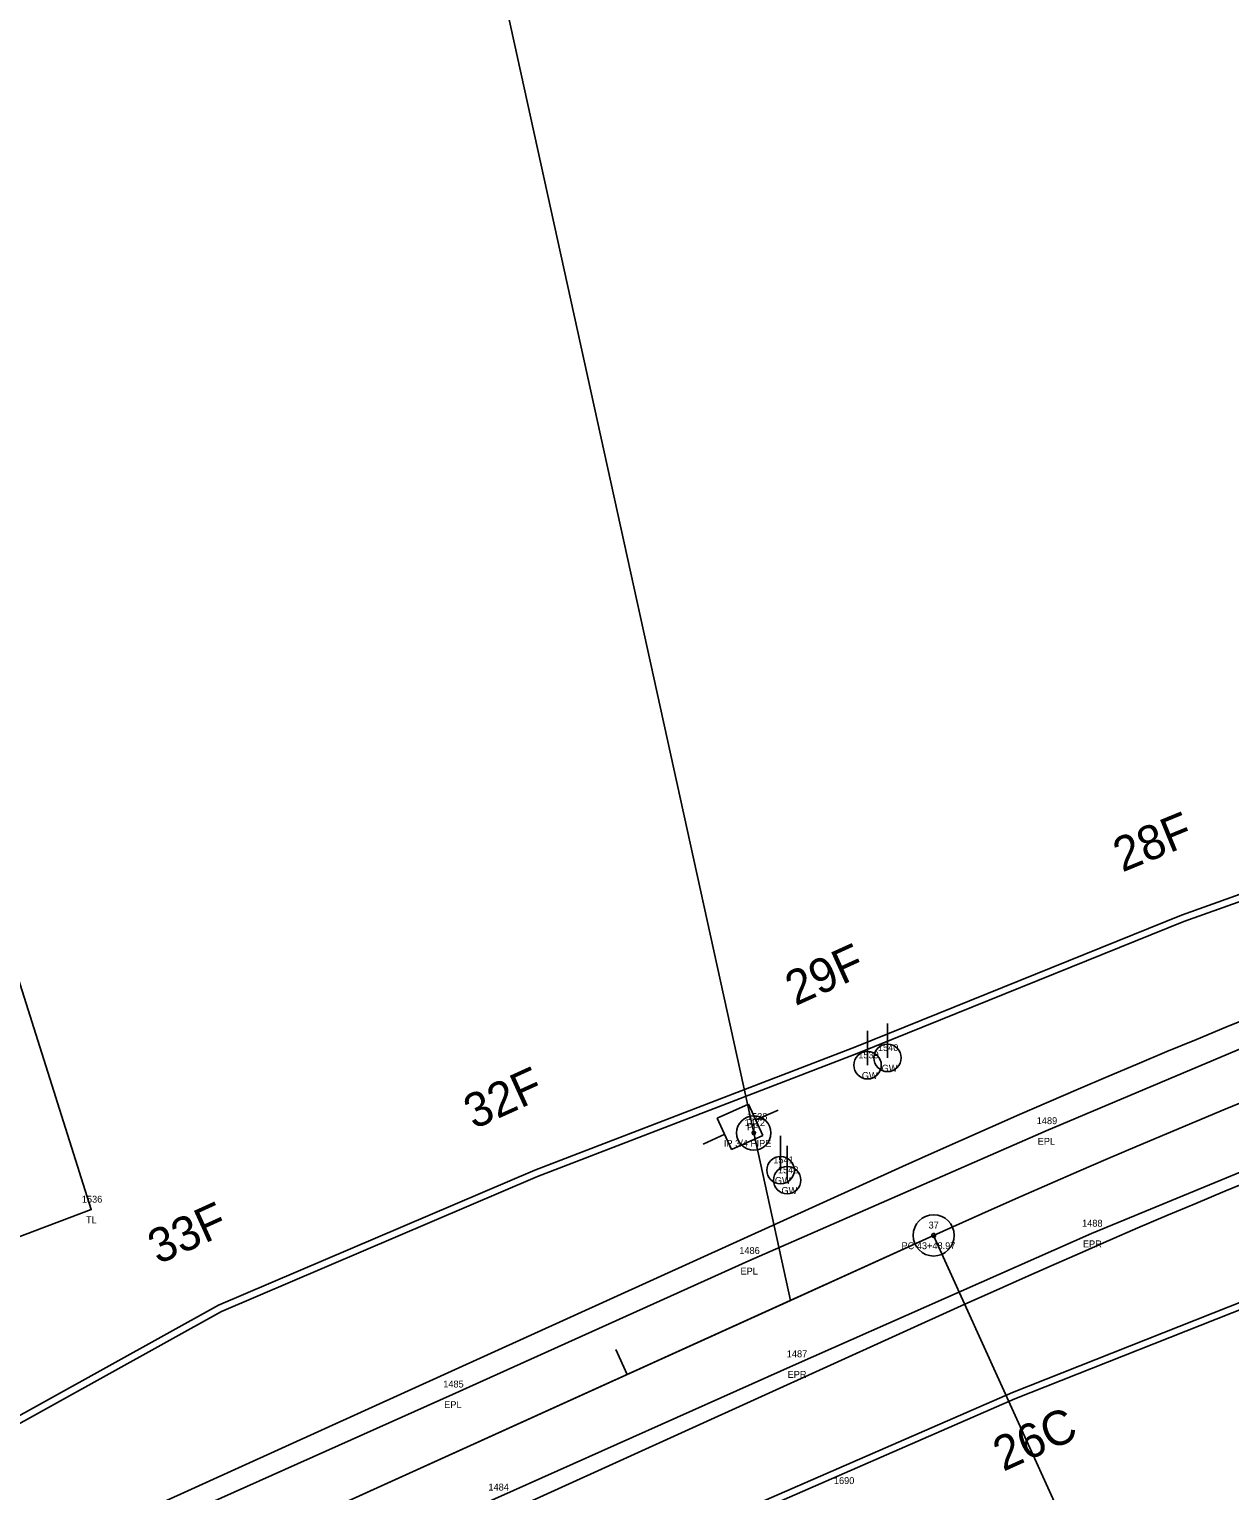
# Model space of a CAD drawing. Extents: x 1964982 to 1970452, y 1116335 to 1119906.
# Drawn here: x 1966013 to 1966187.8, y 1117238.1 to 1117450.8 of the extents above; entities that cross this region are included whole.
import ezdxf

# ---------------------------------------------------------------- set-up
doc = ezdxf.new("R2010")
doc.units = 0
for name, color, linetype in [('RD_EX_DV_Prop', 7, 'Continuous'), ('RD_EX_DV_Prop_txCode', 7, 'Continuous'), ('RD_EX_DV_PropPin', 7, 'Continuous'), ('RD_EX_Road', 7, 'Continuous'), ('RD_EX_Road_txCode', 7, 'Continuous'), ('RD_EX_RW', 7, 'Continuous'), ('RD_EX_UT', 7, 'Continuous'), ('RD_EX_UT_txCode', 7, 'Continuous'), ('RD_EX_VEG', 7, 'Continuous'), ('RD_EX_VEG_txCode', 7, 'Continuous'), ('RD_HC_CL', 7, 'Continuous'), ('RD_HC_Data', 7, 'Continuous'), ('RD_HC_Data_Tic', 7, 'Continuous'), ('RD_HC_txCode', 7, 'Continuous'), ('RD_PD_CstnLmt', 7, 'Continuous'), ('RD_PD_Final_TrvlWay', 7, 'Continuous'), ('RD_PD_RW', 7, 'Continuous'), ('RD_PD_TX_CstnLmt', 7, 'Continuous'), ('RD_SMD_Locator', 7, 'Continuous')]:
    doc.layers.add(name, color=color, linetype=linetype)

msp = doc.modelspace()

# ---------------------------------------------------------------- linework, layer by layer
at = {"layer": 'RD_EX_DV_Prop'}
for p, q in [((1965856.7, 1118481.39), (1966118.52, 1117290.19)), ((1966123.86, 1117265.83), (1966118.52, 1117290.19)), ((1966123.86, 1117265.83), (1966144.7, 1117275.28)), ((1966123.86, 1117265.83), (1965826.85, 1117131.21))]:
    msp.add_line(p, q, dxfattribs=at)
msp.add_arc((1966705.48, 1116038.04), 1358.39, 101.90473, 114.38256, dxfattribs=at)
at = {"layer": 'RD_EX_DV_PropPin'}
for radius in [2.5, 2.5, 0.25, 0.25]:
    msp.add_circle((1966118.52, 1117290.19), radius, dxfattribs=at)
at = {"layer": 'RD_EX_Road'}
for points in [[(1965729.99, 1117080.3), (1965819.77, 1117119.13), (1965907.74, 1117159.31), (1965995.36, 1117199.04), (1966039.27, 1117218.5), (1966081.24, 1117237.15), (1966124.67, 1117256.55), (1966167.66, 1117275.55), (1966211.47, 1117293.63), (1966257.79, 1117311.58), (1966302.7, 1117327.21), (1966347.9, 1117339.98), (1966394.81, 1117351.64), (1966441.56, 1117361.87), (1966488.62, 1117372.06), (1966534.91, 1117381.34), (1966581.23, 1117390.95), (1966629.53, 1117400.95), (1966675.63, 1117411.11), (1966721.68, 1117422.85), (1966766.8, 1117438.97), (1966775.75, 1117440.57)], [(1965723.84, 1117094.48), (1965813.3, 1117133.71), (1965900.46, 1117173.51), (1965988.47, 1117213.41), (1966031.82, 1117232.96), (1966074.66, 1117252.15), (1966117.78, 1117271.58), (1966161.06, 1117290.48), (1966205.41, 1117309.23), (1966251.25, 1117327.39), (1966297.25, 1117343.1), (1966344.08, 1117357.04)]]:
    msp.add_lwpolyline(points, dxfattribs=at)
at = {"layer": 'RD_EX_RW'}
for points in [[(1965729.99, 1117080.3), (1965819.77, 1117119.13), (1965907.74, 1117159.31), (1965995.36, 1117199.04), (1966039.27, 1117218.5), (1966081.24, 1117237.15), (1966124.67, 1117256.55), (1966167.66, 1117275.55), (1966211.47, 1117293.63), (1966257.79, 1117311.58), (1966302.7, 1117327.21), (1966347.9, 1117339.98), (1966394.81, 1117351.64), (1966441.56, 1117361.87), (1966488.62, 1117372.06), (1966534.91, 1117381.34), (1966581.23, 1117390.95), (1966629.53, 1117400.95), (1966675.63, 1117411.11), (1966721.68, 1117422.85), (1966766.8, 1117438.97), (1966775.75, 1117440.57)], [(1965723.84, 1117094.48), (1965813.3, 1117133.71), (1965900.46, 1117173.51), (1965988.47, 1117213.41), (1966031.82, 1117232.96), (1966074.66, 1117252.15), (1966117.78, 1117271.58), (1966161.06, 1117290.48), (1966205.41, 1117309.23), (1966251.25, 1117327.39), (1966297.25, 1117343.1), (1966344.08, 1117357.04)]]:
    msp.add_lwpolyline(points, dxfattribs=at)
at = {"layer": 'RD_EX_UT'}
for p, q in [((1966137.98, 1117301.12), (1966137.98, 1117306.12)), ((1966137.98, 1117301.12), (1966137.98, 1117306.12)), ((1966135.08, 1117300.05), (1966135.08, 1117305.05)), ((1966135.08, 1117300.05), (1966135.08, 1117305.05)), ((1966117.75, 1117294.39), (1966113.19, 1117292.33)), ((1966119.81, 1117289.84), (1966117.75, 1117294.39)), ((1966118.74, 1117292.03), (1966122.06, 1117293.53)), ((1966113.19, 1117292.33), (1966115.26, 1117287.77)), ((1966111.13, 1117288.58), (1966114.29, 1117290.01)), ((1966115.26, 1117287.77), (1966119.81, 1117289.84)), ((1966122.42, 1117284.78), (1966122.42, 1117289.78)), ((1966122.42, 1117284.78), (1966122.42, 1117289.78)), ((1966123.38, 1117283.32), (1966123.38, 1117288.32)), ((1966123.38, 1117283.32), (1966123.38, 1117288.32))]:
    msp.add_line(p, q, dxfattribs=at)
for centre in [(1966135.08, 1117300.05), (1966135.08, 1117300.05), (1966137.98, 1117301.12), (1966137.98, 1117301.12), (1966122.42, 1117284.78), (1966122.42, 1117284.78), (1966123.38, 1117283.32), (1966123.38, 1117283.32)]:
    msp.add_circle(centre, 2, dxfattribs=at)
at = {"layer": 'RD_EX_VEG'}
msp.add_lwpolyline([(1965796.29, 1117182.97), (1965882.08, 1117216.4), (1965973.18, 1117260.57), (1966022.07, 1117279.05), (1966001.07, 1117345.48)], dxfattribs=at)
at = {"layer": 'RD_HC_CL'}
msp.add_line((1965826.85, 1117131.21), (1966144.7, 1117275.28), dxfattribs=at)
msp.add_arc((1966705.48, 1116038.04), 1358.39, 101.90472, 114.38256, dxfattribs=at)
at = {"layer": 'RD_HC_Data'}
msp.add_line((1966144.7, 1117275.28), (1966185.57, 1117185.1), dxfattribs=at)
for radius in [3, 0.282]:
    msp.add_circle((1966144.7, 1117275.28), radius, dxfattribs=at)
at = {"layer": 'RD_HC_Data_Tic'}
msp.add_line((1966100.09, 1117255.06), (1966098.44, 1117258.7), dxfattribs=at)
at = {"layer": 'RD_PD_CstnLmt'}
for p, q in [((1966229.15, 1117338.16), (1966181.14, 1117320.96)), ((1966181.14, 1117320.96), (1966133.81, 1117301.83)), ((1966133.81, 1117301.83), (1966087.03, 1117283.87)), ((1966087.03, 1117283.87), (1966041.05, 1117264.21)), ((1966201.77, 1117270.48), (1966156.16, 1117252.44)), ((1966041.05, 1117264.21), (1965997.17, 1117239.92)), ((1966156.16, 1117252.44), (1966110.33, 1117232.47))]:
    msp.add_line(p, q, dxfattribs=at)
at = {"layer": 'RD_PD_Final_TrvlWay'}
for p, q in [((1965913.39, 1117182.51), (1966140.16, 1117285.29)), ((1965922.47, 1117162.47), (1966149.24, 1117265.26))]:
    msp.add_line(p, q, dxfattribs=at)
for radius in [1369.39, 1347.39]:
    msp.add_arc((1966705.48, 1116038.04), radius, 101.90472, 114.38256, dxfattribs=at)
at = {"layer": 'RD_PD_RW'}
for p, q in [((1966228.83, 1117339.11), (1966180.78, 1117321.89)), ((1966180.78, 1117321.89), (1966133.45, 1117302.77)), ((1966133.45, 1117302.77), (1966086.66, 1117284.8)), ((1966086.66, 1117284.8), (1966040.61, 1117265.11)), ((1966202.12, 1117269.55), (1966156.54, 1117251.52)), ((1966040.61, 1117265.11), (1965996.71, 1117240.81)), ((1966156.54, 1117251.52), (1966110.74, 1117231.56))]:
    msp.add_line(p, q, dxfattribs=at)
at = {"layer": 'RD_SMD_Locator'}
for centre in [(1966161.06, 1117290.48), (1966161.06, 1117290.48), (1966022.07, 1117279.05), (1966022.07, 1117279.05), (1966144.7, 1117275.28), (1966144.7, 1117275.28), (1966167.66, 1117275.55), (1966167.66, 1117275.55), (1966117.78, 1117271.58), (1966117.78, 1117271.58), (1966124.67, 1117256.55), (1966124.67, 1117256.55), (1966074.66, 1117252.15), (1966074.66, 1117252.15)]:
    msp.add_circle(centre, 0.001, dxfattribs=at)

# ---------------------------------------------------------------- texts
at = {"layer": 'RD_EX_DV_Prop_txCode'}
for s, p in [('1472', (1966117.17, 1117291.19)), ('1472', (1966117.17, 1117291.19)), ('IP 3/4 PIPE', (1966114.16, 1117288.19)), ('IP 3/4 PIPE', (1966114.16, 1117288.19))]:
    msp.add_text(s, height=1, dxfattribs=at).set_placement(p)
at = {"layer": 'RD_EX_Road_txCode'}
for s, p in [('1489', (1966159.71, 1117291.48)), ('1489', (1966159.71, 1117291.48)), ('EPL', (1966159.85, 1117288.48)), ('EPL', (1966159.85, 1117288.48)), ('1488', (1966166.31, 1117276.55)), ('1488', (1966166.31, 1117276.55)), ('EPR', (1966166.43, 1117273.55)), ('EPR', (1966166.43, 1117273.55)), ('1486', (1966116.41, 1117272.58)), ('1486', (1966116.41, 1117272.58)), ('EPL', (1966116.58, 1117269.58)), ('EPL', (1966116.58, 1117269.58)), ('1487', (1966123.32, 1117257.55)), ('1487', (1966123.32, 1117257.55)), ('EPR', (1966123.44, 1117254.55)), ('EPR', (1966123.44, 1117254.55)), ('1485', (1966073.31, 1117253.15)), ('1485', (1966073.31, 1117253.15)), ('EPL', (1966073.45, 1117250.15)), ('EPL', (1966073.45, 1117250.15)), ('1484', (1966079.89, 1117238.15)), ('1484', (1966079.89, 1117238.15))]:
    msp.add_text(s, height=1, dxfattribs=at).set_placement(p)
at = {"layer": 'RD_EX_UT_txCode'}
for s, p in [('1539', (1966133.73, 1117301.05)), ('1539', (1966133.73, 1117301.05)), ('1540', (1966136.59, 1117302.12)), ('1540', (1966136.59, 1117302.12)), ('GW', (1966137.13, 1117299.12)), ('GW', (1966137.13, 1117299.12)), ('GW', (1966134.24, 1117298.05)), ('GW', (1966134.24, 1117298.05)), ('1538', (1966117.52, 1117292.08)), ('1538', (1966117.52, 1117292.08)), ('PP', (1966117.52, 1117290.58)), ('PP', (1966117.52, 1117290.58)), ('1541', (1966121.36, 1117285.78)), ('1541', (1966121.36, 1117285.78)), ('1542', (1966122.03, 1117284.32)), ('1542', (1966122.03, 1117284.32)), ('GW', (1966121.58, 1117282.78)), ('GW', (1966121.58, 1117282.78)), ('GW', (1966122.54, 1117281.32)), ('GW', (1966122.54, 1117281.32))]:
    msp.add_text(s, height=1, dxfattribs=at).set_placement(p)
at = {"layer": 'RD_EX_VEG_txCode'}
for s, p in [('1536', (1966020.7, 1117280.05)), ('1536', (1966020.7, 1117280.05)), ('TL', (1966021.3, 1117277.05)), ('TL', (1966021.3, 1117277.05)), ('1690', (1966130.18, 1117239.1))]:
    msp.add_text(s, height=1, dxfattribs=at).set_placement(p)
at = {"layer": 'RD_HC_txCode'}
for s, p in [('37', (1966143.96, 1117276.28)), ('37', (1966143.96, 1117276.28)), ('PC 43+48.97', (1966140.02, 1117273.28)), ('PC 43+48.97', (1966140.02, 1117273.28))]:
    msp.add_text(s, height=1, dxfattribs=at).set_placement(p)
at = {"layer": 'RD_PD_TX_CstnLmt'}
for s, rotation, p in [('28F', 22.2302, (1966172.16, 1117328.09)), ('29F', 24.3391, (1966124.58, 1117308.63)), ('32F', 24.3826, (1966077.79, 1117290.67)), ('33F', 24.3826, (1966031.81, 1117271.01)), ('26C', 24.3391, (1966154.84, 1117240.87))]:
    msp.add_text(s, height=5, rotation=rotation, dxfattribs=at).set_placement(p)

doc.saveas('drawing.dxf')
